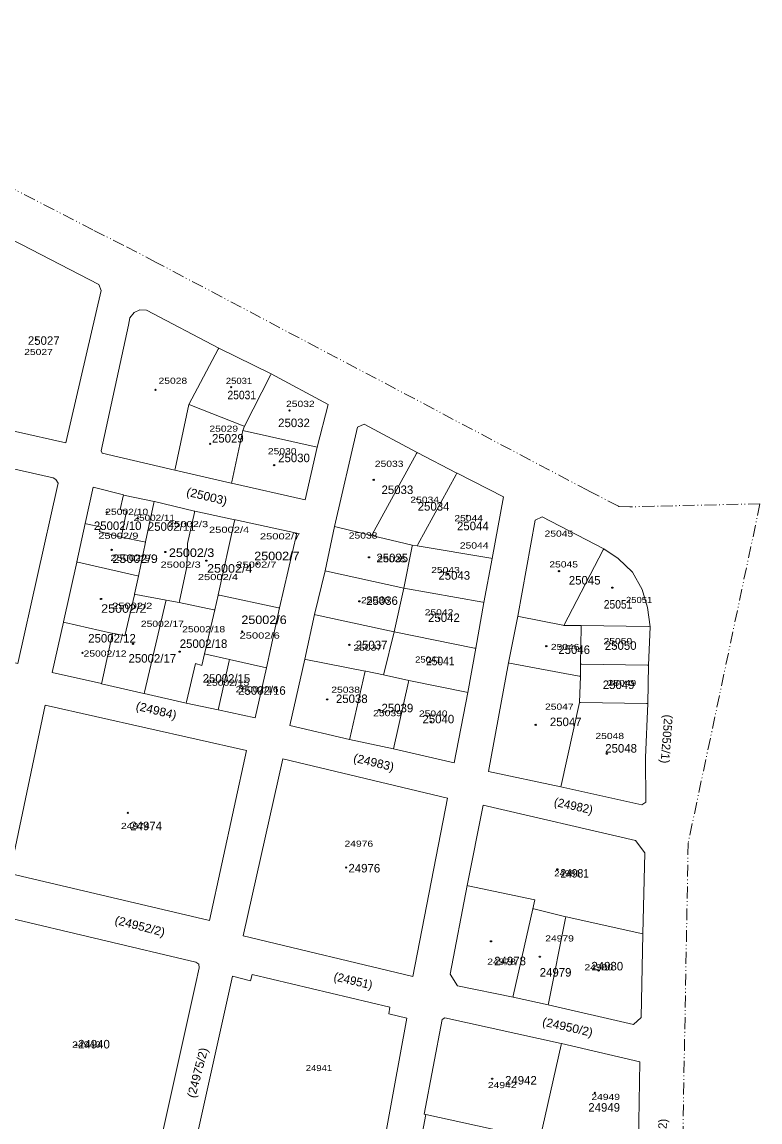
# Model space of a CAD drawing. Extents: x 649608 to 651081, y 237980 to 241202.
# Drawn here: x 650294 to 650605.4, y 240504.6 to 240969 of the extents above; entities that cross this region are included whole.
import ezdxf

# ---------------------------------------------------------------- set-up
doc = ezdxf.new("R2010")
doc.units = 0
doc.header["$PDMODE"] = 32
doc.header["$PDSIZE"] = 0.5
doc.linetypes.add('DASH_DOUBLE_DOT', pattern=[9.2, 5, -1.2, 0.3, -1.2, 0.3, -1.2])
for name, color, linetype in [('19', 7, 'Continuous'), ('20', 7, 'Continuous'), ('6', 7, 'Continuous')]:
    doc.layers.add(name, color=color, linetype=linetype)
for name, color, linetype, lineweight in [('3', 7, 'Continuous', 13), ('5', 7, 'Continuous', 13), ('52', 7, 'DASH_DOUBLE_DOT', 13)]:
    doc.layers.add(name, color=color, linetype=linetype, lineweight=lineweight)

msp = doc.modelspace()

# ---------------------------------------------------------------- linework, layer by layer
at = {"layer": '3'}
for p, q in [((650413.44, 240767.292), (650382.358, 240774.28)), ((650392.39, 240675.174), (650397.096, 240696.312)), ((650554.749, 240529.941), (650521.636, 240537.673)), ((650464.38, 240507.741), (650459.782, 240483.398))]:
    msp.add_line(p, q, dxfattribs=at)
for points in [[(650287.174, 240878.478), (650293.731, 240875.063), (650326.436, 240858.215), (650327.368, 240855.592), (650312.463, 240791.324), (650269.845, 240800.921), (650226.422, 240810.518)], [(650358.438, 240779.811), (650327.791, 240786.88), (650327.356, 240787.87), (650338.893, 240841.012), (650339.522, 240844.046), (650341.338, 240846.319), (650343.74, 240847.503), (650346.455, 240847.299), (650377.056, 240831.309), (650399.126, 240820.396)], [(650399.126, 240820.396), (650423.145, 240807.56), (650418.565, 240789.551), (650413.44, 240767.292)], [(650460.667, 240787.268), (650460.513, 240787.348), (650438.436, 240799.205), (650435.557, 240797.918), (650425.89, 240756.036), (650421.919, 240737.286), (650417.342, 240718.805), (650413.296, 240700.005)], [(650223.417, 240795.43), (650307.133, 240776.57), (650308.295, 240775.78), (650309.204, 240774.353), (650308.746, 240772.419), (650292.209, 240698.101), (650206.497, 240717.549)], [(650492.347, 240742.541), (650497.141, 240768.472), (650477.566, 240778.46), (650477.529, 240778.479), (650460.667, 240787.268)], [(650382.358, 240774.28), (650382.307, 240774.291), (650358.472, 240779.803), (650358.438, 240779.811)], [(650320.564, 240757.256), (650323.985, 240772.551), (650336.774, 240769.292), (650336.808, 240769.285), (650349.729, 240766.535)], [(650349.729, 240766.535), (650349.86, 240766.507), (650366.821, 240762.423)], [(650366.821, 240762.423), (650366.876, 240762.41), (650383.788, 240758.862)], [(650317.047, 240741.001), (650317.051, 240741.018), (650320.564, 240757.256)], [(650383.788, 240758.862), (650384.038, 240758.81), (650410.01, 240753.115), (650402.648, 240721.603), (650397.096, 240696.312)], [(650503.184, 240718.14), (650510.571, 240758.618), (650513.449, 240760.004), (650539.46, 240746.607)], [(650539.46, 240746.607), (650545.623, 240742.504), (650551.549, 240736.712), (650555.628, 240729.366), (650558.001, 240721.784), (650559.046, 240713.697), (650558.424, 240697.428), (650558.026, 240681.31), (650557.079, 240658.483), (650557.181, 240639.662)], [(650311.49, 240715.628), (650311.523, 240715.776), (650317.047, 240741.001)], [(650485.452, 240704.565), (650485.463, 240704.627), (650488.878, 240723.894), (650492.347, 240742.541)], [(650327.497, 240689.643), (650306.744, 240694.29), (650311.49, 240715.628)], [(650499.205, 240698.375), (650499.222, 240698.47), (650503.184, 240718.14)], [(650476.301, 240656.169), (650482.069, 240685.906), (650485.452, 240704.565)], [(650413.296, 240700.005), (650406.936, 240672.002), (650432.207, 240666.028), (650450.728, 240662.166), (650476.301, 240656.169)], [(650521.385, 240646.078), (650521.352, 240646.085), (650490.824, 240652.547), (650499.205, 240698.375)], [(650345.509, 240685.49), (650345.428, 240685.509), (650327.583, 240689.624), (650327.497, 240689.643)], [(650392.39, 240675.174), (650376.786, 240678.611), (650363.222, 240681.442), (650345.509, 240685.49)], [(650557.181, 240639.662), (650555.607, 240638.509), (650521.385, 240646.078)], [(650481.816, 240604.409), (650488.652, 240638.377), (650552.84, 240623.441), (650556.776, 240618.18), (650556.021, 240584.082), (650555.226, 240548.692)], [(650501.189, 240557.344), (650477.71, 240562.092), (650474.656, 240566.962), (650481.816, 240604.409)], [(650367.209, 240562.582), (650368.783, 240569.636), (650368.608, 240571.167), (650367.259, 240572.096), (650286.579, 240591.249), (650284.955, 240591.124), (650284.131, 240589.969), (650282.457, 240582.689), (650264.467, 240501.506)], [(650382.8, 240566.096), (650390.42, 240564.238), (650391.17, 240566.849), (650449.212, 240553.017), (650448.712, 240550.281), (650456.358, 240548.398)], [(650264.467, 240501.506), (650306.865, 240492.557), (650349.449, 240482.852), (650367.209, 240562.582)], [(650382.8, 240566.096), (650352.577, 240429.937), (650351.943, 240426.301), (650353.603, 240422.893), (650357.329, 240422.137), (650359.471, 240422.441), (650359.933, 240419.311), (650429.951, 240429.763), (650429.439, 240432.969), (650433.112, 240433.476), (650435.814, 240436.102), (650436.576, 240439.789), (650456.358, 240548.398)], [(650555.226, 240548.692), (650552.034, 240545.813), (650516.064, 240554.073), (650501.189, 240557.344)], [(650521.636, 240537.673), (650521.523, 240537.699), (650472.342, 240548.546), (650471.343, 240547.893), (650463.651, 240507.86), (650464.38, 240507.741)], [(650511.154, 240442.644), (650511.32, 240442.669), (650553.356, 240448.971), (650553.746, 240471.66), (650554.168, 240496.192), (650554.749, 240529.941)]]:
    msp.add_lwpolyline(points, dxfattribs=at)
for points in [[(650373.055, 240589.718), (650388.724, 240661.431), (650303.719, 240680.522), (650288.878, 240609.549)], [(650458.957, 240566.071), (650387.322, 240583.116), (650404.013, 240657.922), (650473.473, 240641.329)]]:
    msp.add_lwpolyline(points, close=True, dxfattribs=at)
at = {"layer": '5'}
for points in [[(650364.332, 240807.53), (650376.788, 240830.809), (650377.056, 240831.309)], [(650387.82, 240798.34), (650398.87, 240819.896), (650399.126, 240820.396)], [(650358.438, 240779.811), (650358.544, 240780.311), (650364.332, 240807.53)], [(650387.82, 240798.34), (650387.32, 240798.536), (650364.832, 240807.334), (650364.332, 240807.53)], [(650382.358, 240774.28), (650382.467, 240774.78), (650387.206, 240796.548), (650387.82, 240798.34)], [(650387.206, 240796.548), (650387.706, 240796.436), (650418.565, 240789.551)], [(650460.667, 240787.268), (650460.394, 240786.768), (650441.795, 240752.652), (650441.522, 240752.152)], [(650477.529, 240778.479), (650477.256, 240777.979), (650461.049, 240748.323), (650460.776, 240747.823)], [(650336.808, 240769.285), (650336.692, 240768.785), (650335.39, 240763.199), (650338.033, 240762.523), (650335.894, 240751.931), (650335.793, 240751.431)], [(650349.729, 240766.535), (650349.622, 240766.035), (650346.076, 240749.497), (650346.057, 240749.402), (650343.176, 240735), (650341.513, 240727.361)], [(650366.821, 240762.423), (650366.708, 240761.923), (650363.767, 240748.88), (650363.494, 240739.022), (650360.38, 240724.402), (650360.273, 240723.902)], [(650335.793, 240751.431), (650335.659, 240751.457), (650326.646, 240753.899), (650327.133, 240755.79), (650321.064, 240757.144), (650320.564, 240757.256)], [(650383.788, 240758.862), (650383.678, 240758.362), (650376.802, 240727.201), (650376.773, 240727.067), (650375.396, 240720.76), (650371.047, 240702.181)], [(650441.522, 240752.152), (650426.39, 240755.912), (650425.89, 240756.036)], [(650492.347, 240742.541), (650491.847, 240742.625), (650460.776, 240747.823), (650458.688, 240748.131), (650441.522, 240752.152)], [(650346.057, 240749.402), (650345.557, 240749.501), (650335.793, 240751.431)], [(650455.165, 240729.906), (650458.591, 240747.631), (650458.688, 240748.131)], [(650539.46, 240746.607), (650539.201, 240746.107), (650522.695, 240714.233), (650529.927, 240714.139)], [(650317.047, 240741.001), (650317.547, 240740.886), (650342.676, 240735.115), (650343.176, 240735)], [(650455.165, 240729.906), (650422.419, 240737.175), (650421.919, 240737.286)], [(650446.537, 240693.32), (650446.66, 240693.82), (650451.006, 240711.501), (650455.165, 240729.906)], [(650488.878, 240723.894), (650488.378, 240723.983), (650455.165, 240729.906)], [(650341.513, 240727.361), (650341.455, 240727.092), (650337.347, 240709.807), (650332.212, 240710.936), (650332.178, 240710.784)], [(650354.813, 240724.905), (650342.014, 240727.269), (650341.513, 240727.361)], [(650354.813, 240724.905), (650354.695, 240724.405), (650345.627, 240685.99), (650345.509, 240685.49)], [(650375.396, 240720.76), (650374.896, 240720.864), (650360.273, 240723.902), (650354.813, 240724.905)], [(650376.773, 240727.067), (650377.273, 240726.961), (650402.148, 240721.709), (650402.648, 240721.603)], [(650332.178, 240710.784), (650331.678, 240710.901), (650311.99, 240715.511), (650311.49, 240715.628)], [(650451.006, 240711.501), (650417.842, 240718.697), (650417.342, 240718.805)], [(650522.695, 240714.233), (650522.195, 240714.333), (650503.684, 240718.04), (650503.184, 240718.14)], [(650332.178, 240710.784), (650327.608, 240690.143), (650327.497, 240689.643)], [(650485.452, 240704.565), (650484.952, 240704.666), (650451.006, 240711.501)], [(650529.927, 240714.139), (650529.919, 240713.639), (650529.683, 240697.897), (650529.683, 240697.894), (650529.598, 240692.757), (650529.184, 240681.631)], [(650529.927, 240714.139), (650530.006, 240714.138), (650558.546, 240713.705), (650559.046, 240713.697)], [(650371.047, 240702.181), (650369.829, 240697.355), (650367.21, 240698.131), (650363.341, 240681.942), (650363.222, 240681.442)], [(650371.047, 240702.181), (650371.547, 240702.068), (650381.517, 240699.824), (650397.096, 240696.312)], [(650381.517, 240699.824), (650381.405, 240699.324), (650376.898, 240679.111), (650376.786, 240678.611)], [(650438.747, 240694.913), (650413.796, 240699.905), (650413.296, 240700.005)], [(650499.205, 240698.375), (650499.705, 240698.283), (650529.098, 240692.849), (650529.598, 240692.757)], [(650529.683, 240697.894), (650530.183, 240697.886), (650557.924, 240697.436), (650558.424, 240697.428)], [(650438.747, 240694.913), (650438.635, 240694.417), (650432.32, 240666.528), (650432.207, 240666.028)], [(650446.537, 240693.32), (650439.038, 240694.855), (650438.747, 240694.913)], [(650482.069, 240685.906), (650481.569, 240686.008), (650457.258, 240690.965), (650457.233, 240690.97), (650446.537, 240693.32)], [(650457.233, 240690.97), (650457.12, 240690.47), (650450.728, 240662.166)], [(650529.184, 240681.631), (650521.495, 240646.578), (650521.385, 240646.078)], [(650529.184, 240681.631), (650529.684, 240681.625), (650557.526, 240681.316), (650558.026, 240681.31)], [(650481.816, 240604.409), (650482.316, 240604.303), (650510.349, 240598.368), (650509.5, 240594.637)], [(650509.5, 240594.637), (650501.3, 240557.844), (650501.189, 240557.344)], [(650509.5, 240594.637), (650510, 240594.514), (650523.403, 240591.218)], [(650523.403, 240591.218), (650523.3, 240590.698), (650516.163, 240554.573), (650516.064, 240554.073)], [(650523.403, 240591.218), (650523.621, 240591.164), (650556.021, 240584.082)], [(650521.636, 240537.673), (650521.522, 240537.173), (650512.428, 240497.215), (650506.903, 240472.938)], [(650554.168, 240496.192), (650553.668, 240496.204), (650512.428, 240497.215), (650464.38, 240507.741)]]:
    msp.add_lwpolyline(points, dxfattribs=at)
at = {"layer": '52'}
for points in [[(650605.404, 240765.589), (650560.735, 240764.555), (650550.489, 240764.279), (650545.807, 240764.444), (650545.649, 240764.537), (650532.911, 240771.119), (650350.609, 240867.503), (650336.954, 240874.591), (650323.91, 240881.206), (650163.407, 240963.863), (650154.776, 240968.319), (650055.166, 241019.937)], [(650605.404, 240765.589), (650575.102, 240622.376), (650564.111, 240019.547), (650563.292, 239912.239), (650561.967, 239831.306), (650558.948, 239635.138), (650557.76, 239590.469), (650555.824, 239499.761), (650555.114, 239481.758), (650553.994, 239393.396), (650554.019, 239393.395), (650553.222, 239318.763), (650553.006, 239301.006), (650586.911, 239277.281)]]:
    msp.add_lwpolyline(points, dxfattribs=at)
at = {"layer": '6'}
for p in [(650300.003, 240834.901), (650350.282, 240813.657), (650382.252, 240814.824), (650406.854, 240804.973), (650373.387, 240790.905), (650400.415, 240781.92), (650442.386, 240775.678), (650460.734, 240767.545), (650329.774, 240761.991), (650342.789, 240759.343), (650481.689, 240760.51), (650331.779, 240746.128), (650354.443, 240745.218), (650440.407, 240742.971), (650371.771, 240741.591), (650393.339, 240740.232), (650473.739, 240736.012), (650520.597, 240737.118), (650543.065, 240730.152), (650327.343, 240725.404), (650436.323, 240724.393), (650470, 240717.235), (650386.872, 240711.689), (650340.832, 240706.425), (650432.134, 240706.062), (650515.212, 240705.448), (650544.272, 240705.783), (650319.487, 240702.635), (650360.481, 240703.173), (650466.125, 240698.703), (650372.388, 240690.396), (650386.951, 240687.499), (650543.856, 240689.602), (650422.745, 240683.016), (650444.733, 240678.539), (650466.49, 240673.569), (650510.772, 240672.226), (650540.8, 240660.07), (650338.6, 240635.12), (650430.79, 240611.996), (650519.905, 240611.229), (650491.875, 240580.876), (650512.525, 240574.355), (650537.294, 240568.515), (650316.933, 240537.05), (650492.403, 240522.88), (650535.72, 240516.932)]:
    msp.add_point(p, dxfattribs=at)

# ---------------------------------------------------------------- texts
at = {"layer": '19'}
for s, p in [('25027', (650296.463, 240832.687)), ('25032', (650402.068, 240797.949)), ('25029', (650374.147, 240791.419)), ('25030', (650402.068, 240783.147)), ('25033', (650445.694, 240769.694)), ('25034', (650460.963, 240762.686)), ('25002/10', (650324.309, 240754.505)), ('25002/11', (650347.091, 240754.166)), ('25044', (650477.542, 240754.415)), ('25035', (650443.513, 240740.919)), ('25043', (650469.689, 240733.519)), ('25045', (650524.728, 240731.487)), ('25036', (650439.188, 240722.883)), ('25042', (650465.327, 240715.67)), ('25002/12', (650321.928, 240707.001)), ('25002/18', (650360.539, 240704.729)), ('25037', (650434.788, 240704.199)), ('25046', (650520.295, 240702.174)), ('25050', (650539.927, 240703.915)), ('25002/17', (650338.931, 240698.518)), ('25002/15', (650370.213, 240690.036)), ('25002/16', (650385.175, 240684.946)), ('25049', (650539.055, 240687.373)), ('25038', (650426.451, 240681.455)), ('25039', (650445.695, 240677.547)), ('25040', (650462.973, 240672.899)), ('25047', (650516.741, 240671.712)), ('25048', (650540.1, 240660.533)), ('24974', (650339.69, 240627.786)), ('24976', (650431.741, 240609.937)), ('24978', (650493.254, 240570.757)), ('24980', (650534.262, 240568.58)), ('24979', (650512.45, 240565.968)), ('24940', (650317.647, 240535.643)), ('24942', (650497.823, 240520.406)), ('24949', (650532.953, 240508.939))]:
    msp.add_text(s, height=3.6, dxfattribs=at).set_placement(p)
for s, width, p in [('25031', 0.9, (650380.691, 240809.703)), ('25002/9', 1.1, (650332.13, 240740.593)), ('25002/3', 1.1, (650355.975, 240743.128)), ('25002/7', 1.1, (650391.976, 240741.753)), ('25002/4', 1.1, (650372.068, 240736.494)), ('25051', 0.9, (650539.491, 240721.329)), ('25002/2', 1.1, (650327.369, 240719.556)), ('25002/6', 1.1, (650386.535, 240714.805)), ('25041', 0.9, (650464.454, 240697.385)), ('24981', 0.9, (650521.175, 240607.761))]:
    msp.add_text(s, height=3.6, dxfattribs=dict(at, width=width)).set_placement(p)
at = {"layer": '19', "width": 1.05}
for s, rotation, p in [('(25003)', 346.411, (650363.091, 240769.038)), ('(24984)', 346.413, (650341.755, 240678.651)), ('(24983)', 346.544, (650433.535, 240656.732)), ('(24952/2)', 345.535, (650332.839, 240588.257)), ('(24950/2)', 347.293, (650513.274, 240545.336)), ('(24975/2)', 75.279, (650367.036, 240514.47))]:
    msp.add_text(s, height=3.6, rotation=rotation, dxfattribs=at).set_placement(p)
at = {"layer": '19'}
for s, rotation, p in [('(25052/1)', 265.77, (650565.009, 240676.68)), ('(24982)', 347.688, (650518.209, 240638.103)), ('(24951)', 346.793, (650425.245, 240564.399)), ('(24833/2)', 88.873, (650565.736, 240485.298))]:
    msp.add_text(s, height=3.6, rotation=rotation, dxfattribs=at).set_placement(p)
at = {"layer": '20'}
for s, width, p in [('25027', 1.25, (650294.897, 240828.362)), ('25028', 1.25, (650351.589, 240816.22)), ('25031', 1.15, (650379.992, 240816.158)), ('25032', 1.25, (650405.392, 240806.466)), ('25029', 1.25, (650373.06, 240795.987)), ('25030', 1.25, (650397.734, 240786.471)), ('25033', 1.25, (650442.868, 240781.166)), ('25034', 1.25, (650457.86, 240765.992)), ('25002/10', 1.25, (650329.095, 240760.891)), ('25002/11', 1.2, (650341.084, 240758.364)), ('25002/3', 1.35, (650355.572, 240755.709)), ('25044', 1.25, (650476.421, 240758.21)), ('25002/9', 1.35, (650326.143, 240750.785)), ('25002/4', 1.35, (650372.893, 240753.307)), ('25002/7', 1.35, (650394.374, 240750.542)), ('25038', 1.25, (650431.879, 240750.895)), ('25045', 1.25, (650514.491, 240751.692)), ('25044', 1.25, (650478.75, 240746.682)), ('25002/9', 1.35, (650331.252, 240741.454)), ('25035', 1.25, (650443.938, 240740.855)), ('25002/3', 1.35, (650352.423, 240738.589)), ('25002/7', 1.35, (650384.417, 240738.589)), ('25043', 1.25, (650466.649, 240736.311)), ('25045', 1.25, (650516.499, 240738.694)), ('25002/4', 1.35, (650368.177, 240733.355)), ('25036', 1.25, (650437.066, 240723.612)), ('25051', 1.15, (650548.832, 240723.681)), ('25002/2', 1.35, (650332.002, 240721.207)), ('25042', 1.25, (650463.902, 240718.476)), ('25002/17', 1.25, (650344.146, 240713.602)), ('25002/18', 1.25, (650361.575, 240711.33)), ('25002/6', 1.35, (650385.779, 240708.664)), ('25037', 1.25, (650433.826, 240703.563)), ('25046', 1.25, (650517.131, 240703.83)), ('25050', 1.25, (650539.389, 240706.299)), ('25002/12', 1.25, (650319.97, 240701.059)), ('25041', 1.15, (650459.853, 240698.526)), ('25002/15', 1.25, (650371.731, 240688.713)), ('25002/16', 1.25, (650384.114, 240685.948)), ('25038', 1.25, (650424.5, 240685.785)), ('25049', 1.25, (650541.095, 240688.62)), ('25039', 1.25, (650442.173, 240675.909)), ('25040', 1.25, (650461.467, 240675.711)), ('25047', 1.25, (650514.681, 240678.645)), ('25048', 1.25, (650535.959, 240666.261)), ('24974', 1.25, (650335.734, 240628.263)), ('24976', 1.25, (650430.071, 240620.783)), ('24981', 1.15, (650518.566, 240608.246)), ('24979', 1.25, (650514.79, 240580.79)), ('24978', 1.25, (650490.316, 240570.988)), ('24980', 1.25, (650531.349, 240568.618)), ('24940', 1.25, (650315.143, 240536.006)), ('24941', 1.15, (650413.719, 240526.074)), ('24942', 1.25, (650490.562, 240518.884)), ('24949', 1.25, (650534.235, 240513.877))]:
    msp.add_text(s, height=2.6, dxfattribs=dict(at, width=width)).set_placement(p)

doc.saveas('drawing.dxf')
